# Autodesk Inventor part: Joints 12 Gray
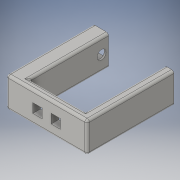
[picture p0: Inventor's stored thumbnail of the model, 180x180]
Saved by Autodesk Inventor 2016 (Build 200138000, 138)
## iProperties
Created: 2015-09
Part Number: Joints 12 Gray
Material: Generic
Document SubType Name: Modeling
Designer: ChombaW
Density: 1 g/cm^3
Appearance: Default
Author: ChombaW
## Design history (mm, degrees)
sketch "Sketch1"
  geometry: L1 (27.165, 10.16)-(-27.165, 10.16); L2 (-27.165, 10.16)-(-27.165, -10.16); L3 (-27.165, -10.16)-(27.165, -10.16); L4 (27.165, -10.16)-(27.165, 10.16); L5 (27.165, 10.16)-(-27.165, -10.16); L6 (-27.165, 10.16)-(27.165, -10.16); 1 further point
  constraints: 12 end point, 2 midpoint, 2 parallel, 1 horizontal, 1 perpendicular
  dimensions: "d0" = 54.3306 distance of L3.end L2.end; "d1" = 20.32 distance of L2.end L1.end
extrude "Extrusion1" new body sketch "Sketch1" distance "d2" = 5.08; taper "d3" = 0 deg
sketch "Sketch2"
  geometry: L1 (-3.061, 2.549)-(-9.284, 2.549); L2 (-9.284, 2.549)-(-9.284, -3.674); L3 (-9.284, -3.674)-(-3.061, -3.674); L4 (-3.061, -3.674)-(-3.061, 2.549); L5 (-3.061, 2.549)-(-9.284, -3.674); L6 (-9.284, 2.549)-(-3.061, -3.674); L7 (9.258, -3.674)-(3.035, -3.674); L8 (3.035, -3.674)-(3.035, 2.549); L9 (3.035, 2.549)-(9.258, 2.549); L10 (9.258, 2.549)-(9.258, -3.674); L11 (9.258, -3.674)-(3.035, 2.549); L12 (3.035, -3.674)-(9.258, 2.549); L13 (27.165, -10.16)-(27.165, 10.16) reference; L14 (-27.165, 10.16)-(-27.165, -10.16) reference; 3 further points
  constraints: 24 end point, 4 midpoint, 4 parallel, 2 horizontal, 2 perpendicular
  dimensions: "d4" = 6.223 distance of L3.end L2.end; "d5" = 6.223 distance of L2.end L1.end; "d6" = 6.223 distance of L8.end L9.end; "d7" = 6.223 distance of L7.end L8.end; "d8" = 12.319 distance of L8.end L1.end; "d9" = 17.907 distance from line of L13 L9.end; "d10" = 17.8816 distance from line of L14 L2.end; "d38" = 6.096 distance between parallel lines of L4 L8 (derived)
extrude "Extrusion2" cut sketch "Sketch2" distance "d11" = 5.08; taper "d12" = 0 deg
sketch "Sketch3"
  geometry: L1 (27.165, 10.16)-(16.65, 10.16); L2 (16.65, 10.16)-(16.65, -10.16); L3 (16.65, -10.16)-(27.165, -10.16); L4 (27.165, -10.16)-(27.165, 10.16); L5 (27.165, 10.16)-(16.65, -10.16); L6 (16.65, 10.16)-(27.165, -10.16); L7 (27.165, -10.16)-(27.165, 10.16) reference; L8 (-21.069, 10.16)-(-27.165, 10.16); L9 (-27.165, 10.16)-(-27.165, -10.16); L10 (-27.165, -10.16)-(-21.069, -10.16); L11 (-21.069, -10.16)-(-21.069, 10.16); L12 (-21.069, 10.16)-(-27.165, -10.16); L13 (-27.165, 10.16)-(-21.069, -10.16); L14 (-27.165, 10.16)-(-27.165, -10.16) reference; 3 further points
  constraints: 24 end point, 4 midpoint, 4 parallel, 2 horizontal, 2 perpendicular
  dimensions: "d13" = 10.5156 distance of L3.end L2.end; "d14" = 20.32 distance of L2.end L1.end; "d15" = 0 distance from line of L7 L1.start; "d16" = 6.096 distance of L10.end L9.end; "d17" = 20.32 distance of L9.end L8.end; "d18" = 0 distance from line of L14 L8.end
extrude "Extrusion3" join sketch "Sketch3" distance "d19" = 53.086; taper "d20" = 0 deg
sketch "Sketch4"
  geometry: L1 (-51.51, 14.427)-(-40.457, 14.427); L2 (-40.457, 14.427)-(-27.428, 12.82); L3 (-27.428, 7.5)-(-40.457, 5.893); L4 (-40.457, 5.893)-(-53.372, 5.439); L5 (-53.372, 5.439)-(-58.166, 5.439); L6 (-58.166, 0)-(-58.166, 20.32) reference; L7 (-53.372, 14.881)-(-58.166, 14.881); A1 r 4.724 centre (-53.538, 10.16) between (-51.51, 14.427) and (-53.372, 5.439); A2 r 4.267 centre (-40.457, 10.16) between (-40.457, 14.427) and (-40.457, 5.893); A3 r 2.68 centre (-27.757, 10.16) between (-27.428, 12.82) and (-27.428, 7.5); 1 further point
  constraints: 12 end point, 7 point on circle, 3 centre point, 3 tangent, 2 point on line, 1 horizontal, 1 parallel
  dimensions: "d21" = 9.4488 diameter of A1; "d22" = 8.5344 diameter of A2; "d23" = 5.3594 diameter of A3; "d24" = 13.081 distance of A2.centre A1.centre; "d25" = 12.7 distance of A3.centre A2.centre
extrude "Extrusion4" cut sketch "Sketch4" distance "d26" = 9.398; taper "d27" = 0 deg
sketch "Sketch5"
  geometry: L1 (-58.166, 14.881)-(-53.372, 14.881) reference; L2 (-53.372, 5.439)-(-58.166, 5.439) reference; C1 r 3.023 at (-53.461, 10.157); 1 further point
  constraints: 1 centre point
  dimensions: "d28" = 6.0452 diameter of C1; "d29" = 4.7244 distance from line of L1 C1.centre; "d30" = 4.71856 distance from line of L2 C1.centre (derived)
extrude "Extrusion5" cut sketch "Sketch5" distance "d31" = 4.4196; taper "d32" = 0 deg
fillet "Fillet1" dims "d33" = 1.5875
fillet "Fillet2" dims "d34" = 1.5875
fillet "Fillet3" dims "d35" = 1.5875
fillet "Fillet4" dims "d36" = 1.5875
fillet "Fillet5" dims "d37" = 1.5875
body "Solid1"
